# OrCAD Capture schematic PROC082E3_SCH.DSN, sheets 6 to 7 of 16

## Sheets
6 06. FPD_LINK_SER3: size C; title: FPD_LINK_SER3
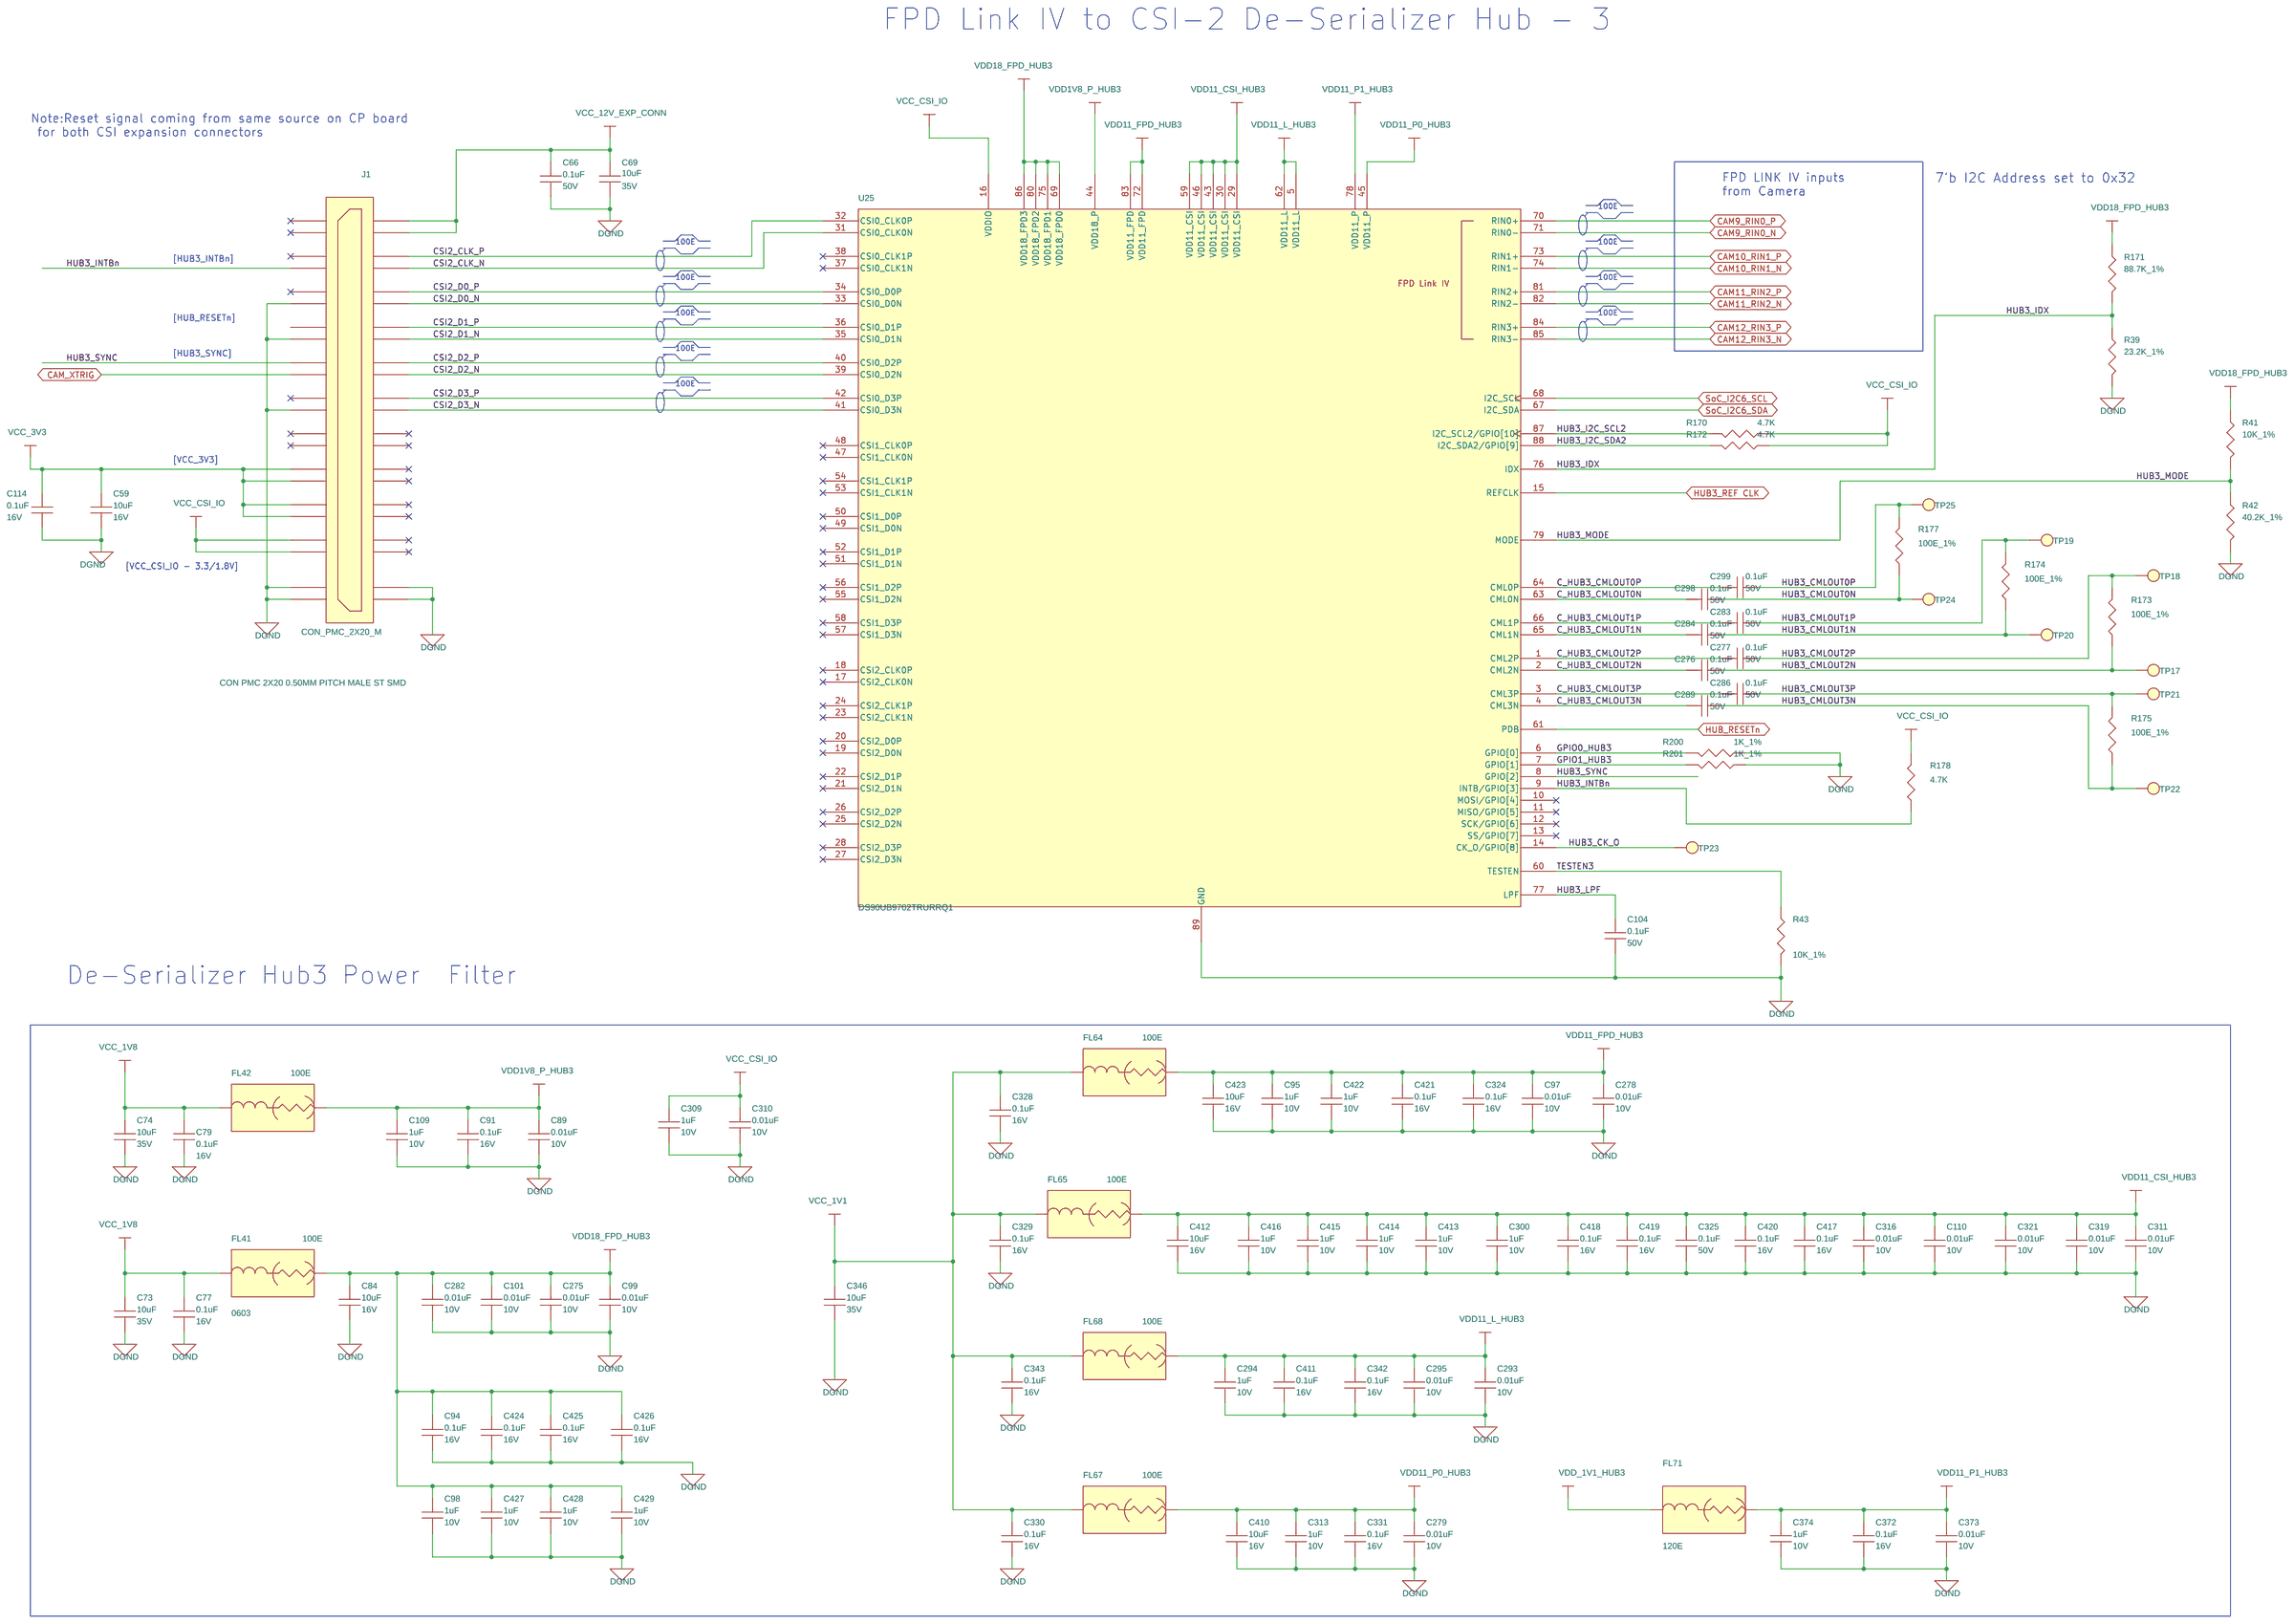
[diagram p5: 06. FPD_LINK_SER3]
7 07. FPD_LINK_971: size C; title: FUSION2_CONN & FPD_LINK_SER1
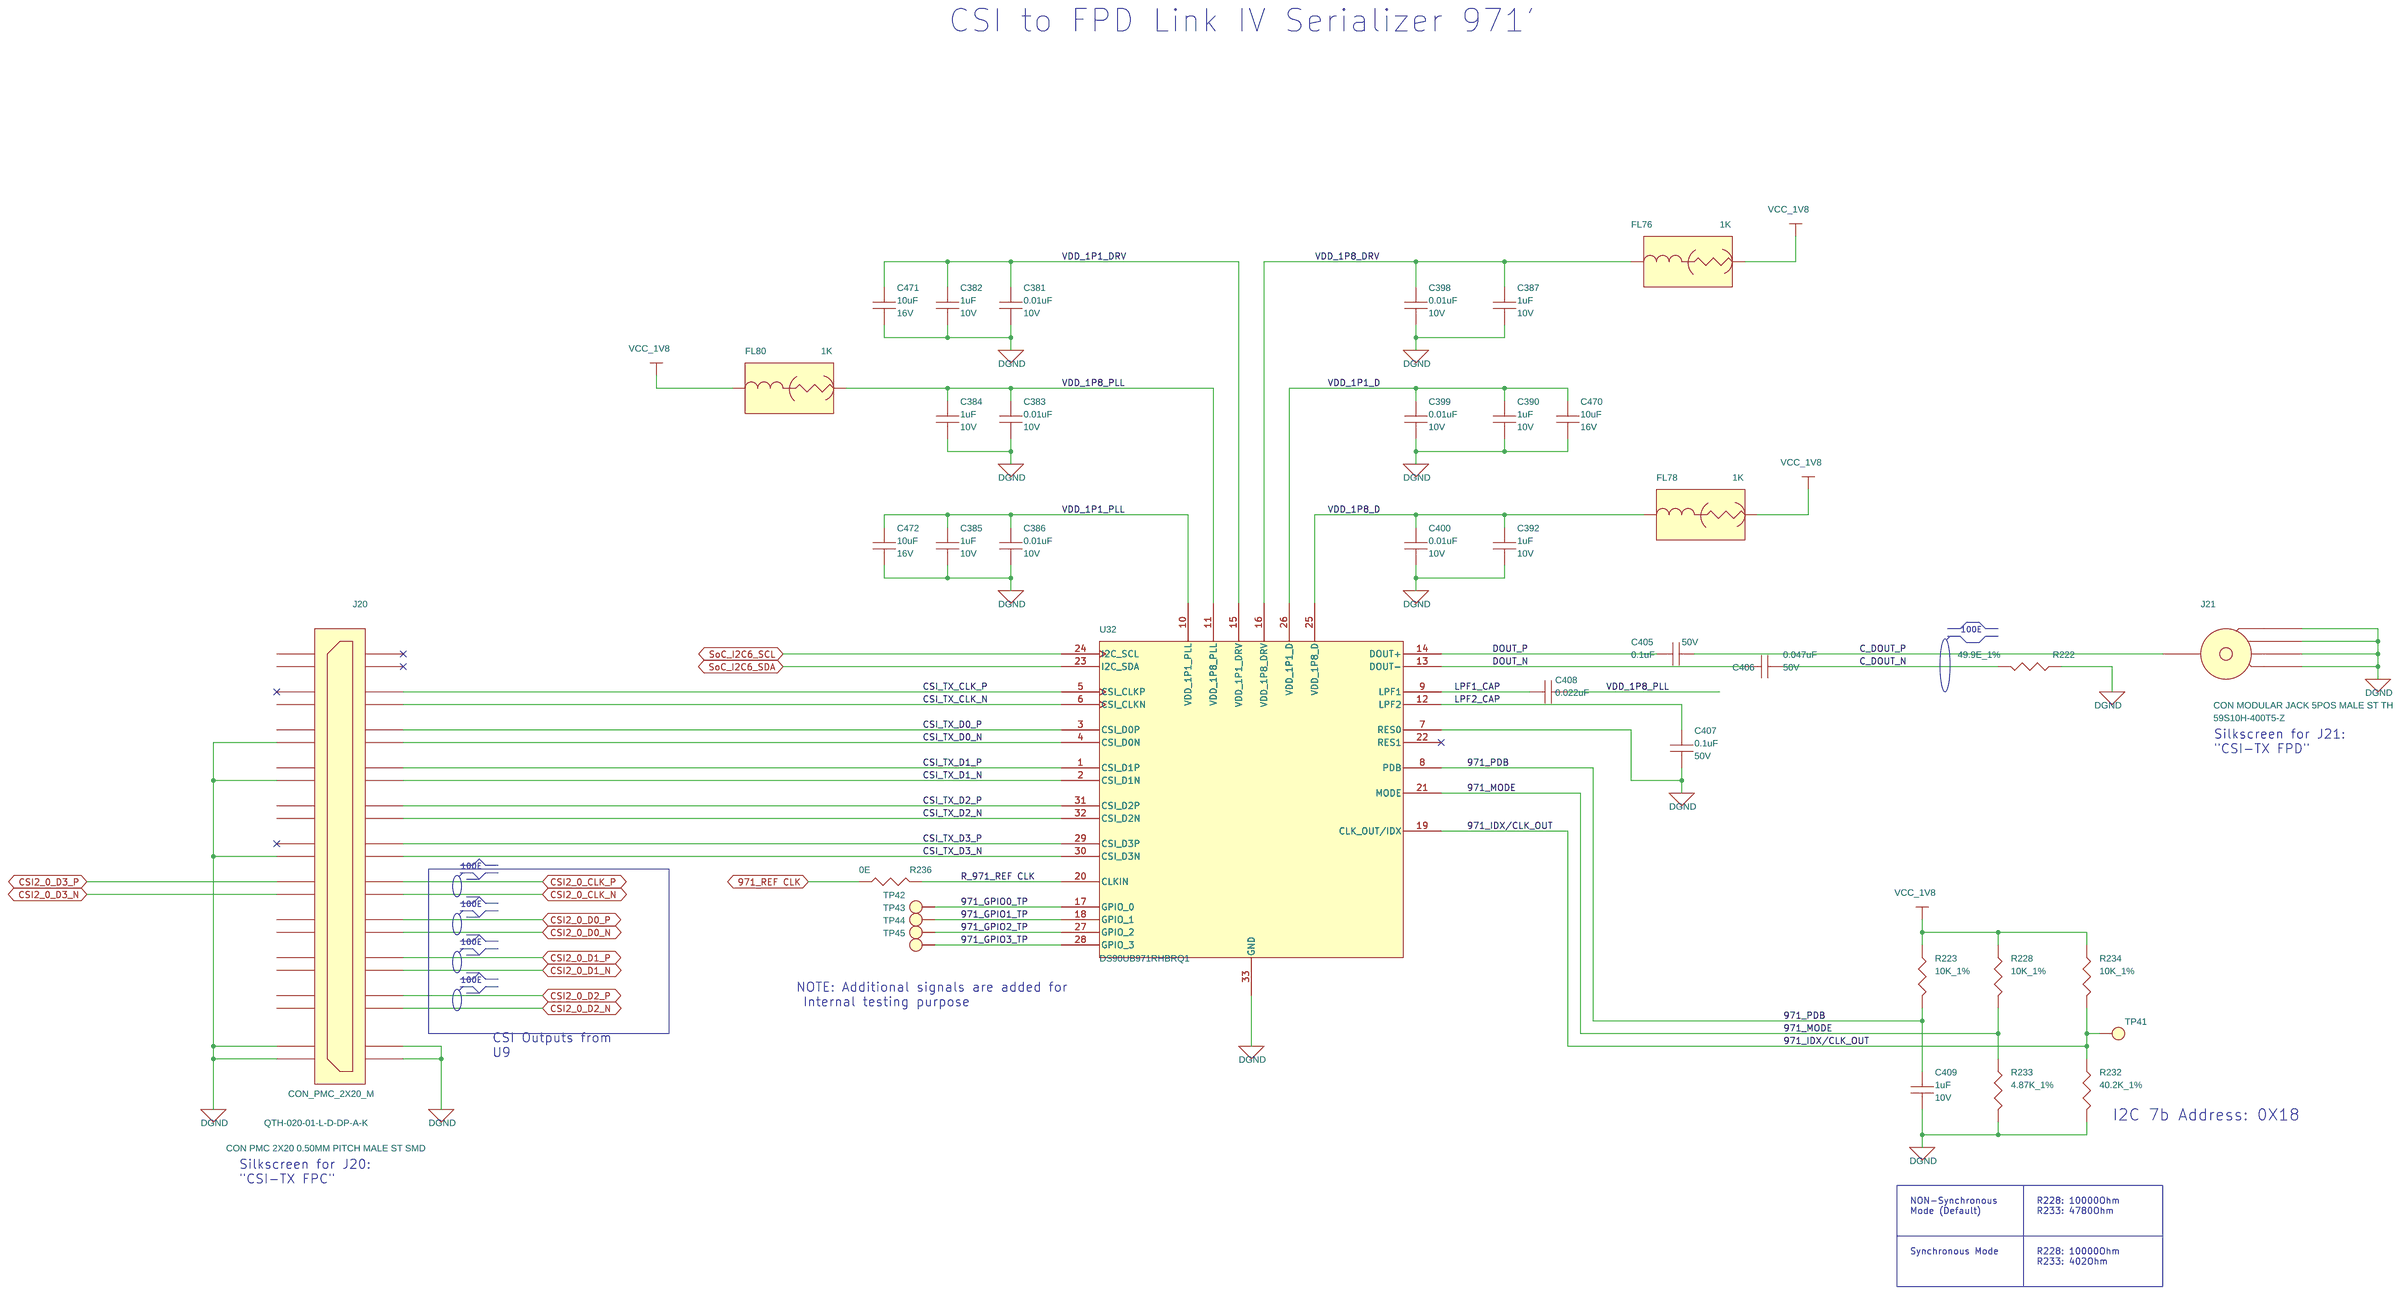
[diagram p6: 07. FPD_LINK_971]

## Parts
sheet 06. FPD_LINK_SER3
C59  10uF  [CAP0603_1]
C66  0.1uF  [CAP0402_0-75]
C69  10uF  [CAP1206_1]
C73  10uF  [CAP1206_1]
C74  10uF  [CAP1206_1]
C77  0.1uF  [CAP0402_0-75]
C79  0.1uF  [CAP0402_0-75]
C84  10uF  [CAP0603_1]
C89  0.01uF  [CAP0201_0-5]
C91  0.1uF  [CAP0402_0-75]
C94  0.1uF  [CAP0402_0-75]
C95  1uF  [CAP0402_0-75]
C97  0.01uF  [CAP0201_0-5]
C98  1uF  [CAP0402_0-75]
C99  0.01uF  [CAP0201_0-5]
C101  0.01uF  [CAP0201_0-5]
C104  0.1uF  [CAP0402_0-75]
C109  1uF  [CAP0402_0-75]
C110  0.01uF  [CAP0201_0-5]
C114  0.1uF  [CAP0402_0-75]
C275  0.01uF  [CAP0201_0-5]
C276  0.1uF  [CAP0402_0-75]
C277  0.1uF  [CAP0402_0-75]
C278  0.01uF  [CAP0201_0-5]
C279  0.01uF  [CAP0201_0-5]
C282  0.01uF  [CAP0201_0-5]
C283  0.1uF  [CAP0402_0-75]
C284  0.1uF  [CAP0402_0-75]
C286  0.1uF  [CAP0402_0-75]
C289  0.1uF  [CAP0402_0-75]
C293  0.01uF  [CAP0201_0-5]
C294  1uF  [CAP0402_0-75]
C295  0.01uF  [CAP0201_0-5]
C298  0.1uF  [CAP0402_0-75]
C299  0.1uF  [CAP0402_0-75]
C300  1uF  [CAP0402_0-75]
C309  1uF  [CAP0402_0-75]
C310  0.01uF  [CAP0201_0-5]
C311  0.01uF  [CAP0201_0-5]
C313  1uF  [CAP0402_0-75]
C316  0.01uF  [CAP0201_0-5]
C319  0.01uF  [CAP0201_0-5]
C321  0.01uF  [CAP0201_0-5]
C324  0.1uF  [CAP0402_0-75]
C325  0.1uF  [CAP0402_0-75]
C328  0.1uF  [CAP0402_0-75]
C329  0.1uF  [CAP0402_0-75]
C330  0.1uF  [CAP0402_0-75]
C331  0.1uF  [CAP0402_0-75]
C342  0.1uF  [CAP0402_0-75]
C343  0.1uF  [CAP0402_0-75]
C346  10uF  [CAP1206_1]
C372  0.1uF  [CAP0402_0-75]
C373  0.01uF  [CAP0201_0-5]
C374  1uF  [CAP0402_0-75]
C410  10uF  [CAP0603_1]
C411  0.1uF  [CAP0402_0-75]
C412  10uF  [CAP0603_1]
C413  1uF  [CAP0402_0-75]
C414  1uF  [CAP0402_0-75]
C415  1uF  [CAP0402_0-75]
C416  1uF  [CAP0402_0-75]
C417  0.1uF  [CAP0402_0-75]
C418  0.1uF  [CAP0402_0-75]
C419  0.1uF  [CAP0402_0-75]
C420  0.1uF  [CAP0402_0-75]
C421  0.1uF  [CAP0402_0-75]
C422  1uF  [CAP0402_0-75]
C423  10uF  [CAP0603_1]
C424  0.1uF  [CAP0402_0-75]
C425  0.1uF  [CAP0402_0-75]
C426  0.1uF  [CAP0402_0-75]
C427  1uF  [CAP0402_0-75]
C428  1uF  [CAP0402_0-75]
C429  1uF  [CAP0402_0-75]
FL41  100E  [EMIFIL_BLM18R_0603]
FL42  100E  [EMIFIL_BLM18R_0603]
FL64  100E  [EMIFIL_BLM18R_0603]
FL65  100E  [EMIFIL_BLM18R_0603]
FL67  100E  [EMIFIL_BLM18R_0603]
FL68  100E  [EMIFIL_BLM18R_0603]
FL71  120E  [EMIFIL_BLM15A_0402_0-6]
J1  CON_PMC_2X20_M  [CON_PMC2X20_QTH-020-01-D-DP-A_P_S_S_4-4]
R39  23.2K_1%  [RES0402_0-5]
R41  10K_1%  [RES0402_0-5]
R42  40.2K_1%  [RES0402_0-5]
R43  10K_1%  [RES0402_0-5]
R170  4.7K  [RES0402_0-5]
R171  88.7K_1%  [RES0402_0-5]
R172  4.7K  [RES0402_0-5]
R173  100E_1%  [RES0402_0-5]
R174  100E_1%  [RES0402_0-5]
R175  100E_1%  [RES0402_0-5]
R177  100E_1%  [RES0402_0-5]
R178  4.7K  [RES0402_0-5]
R200  1K_1%  [RES0402_0-5]
R201  1K_1%  [RES0402_0-5]
TP17  TP40_SMD  [TP40_SMD]
TP18  TP40_SMD  [TP40_SMD]
TP19  TP40_SMD  [TP40_SMD]
TP20  TP40_SMD  [TP40_SMD]
TP21  TP40_SMD  [TP40_SMD]
TP22  TP40_SMD  [TP40_SMD]
TP23  TP40_SMD  [TP40_SMD]
TP24  TP40_SMD  [TP40_SMD]
TP25  TP40_SMD  [TP40_SMD]
U25  DS90UB9702TRURRQ1  [QFN88_19-68_480X480_0-9_EP6-8]
sheet 07. FPD_LINK_971
C381  0.01uF  [CAP0201_0-5]
C382  1uF  [CAP0402_0-75]
C383  0.01uF  [CAP0201_0-5]
C384  1uF  [CAP0402_0-75]
C385  1uF  [CAP0402_0-75]
C386  0.01uF  [CAP0201_0-5]
C387  1uF  [CAP0402_0-75]
C390  1uF  [CAP0402_0-75]
C392  1uF  [CAP0402_0-75]
C398  0.01uF  [CAP0201_0-5]
C399  0.01uF  [CAP0201_0-5]
C400  0.01uF  [CAP0201_0-5]
C405  0.1uF  [CAP0402_0-75]
C406  0.047uF  [CAP0402_0-75]
C407  0.1uF  [CAP0402_0-75]
C408  0.022uF  [CAP0402_0-75]
C409  1uF  [CAP0402_0-75]
C470  10uF  [CAP0603_1]
C471  10uF  [CAP0603_1]
C472  10uF  [CAP0603_1]
FL76  1K  [EMIFIL_BLM15A_0402_0-6]
FL78  1K  [EMIFIL_BLM15A_0402_0-6]
FL80  1K  [EMIFIL_BLM15A_0402_0-6]
J20  CON_PMC_2X20_M  [CON_PMC2X20_QTH-020-01-D-DP-A_P_S_S_4-4]
J21  CON_JACK5_59S10H-400T5  [CON_JACK5_59S10H-400T5-Z_P_S_T_12-5]
R222  49.9E_1%  [RES0402_0-5]
R223  10K_1%  [RES0402_0-5]
R228  10K_1%  [RES0402_0-5]
R232  40.2K_1%  [RES0402_0-5]
R233  4.87K_1%  [RES0402_0-5]
R234  10K_1%  [RES0402_0-5]
R236  0E  [RES0402_0-5]
TP41  TP40_SMD  [TP40_SMD]
TP42  TP40_SMD  [TP40_SMD]
TP43  TP40_SMD  [TP40_SMD]
TP44  TP40_SMD  [TP40_SMD]
TP45  TP40_SMD  [TP40_SMD]
U32  DS90UB971RHBRQ1  [QFN32_19-68_200X200_1_EP3-8]

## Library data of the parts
C59 C84 C410 C412 C423 C470-C472 = CAP: CAP CERAMIC 10uF 16V 20% X6S 0603; Chkd/date: VASANTHA/170117; Crtd /date: VASANTHA/170117; Custom_Duty: 15%; Customs_HS_Code: 85322990; Distributor_name: DIGIKEY; Distributor_part_number: 490-7198-1-ND; Footprint Path: Y:\MIS_DATABASE\Library\ALTIUM_TOOL\PCB_FOOTPRINTS\Altium_Footprint_Lib.PcbLib; Height: 0.90MM; Library Path: Y:\MIS_DATABASE\Library\ALTIUM_TOOL\SCHEMATICS_PARTS\MS_DISCRETE_Library.schlib; Mfr_name: MURATA; Mfr_part_number: GRM188C81C106MA73D; Mistral Part No: 120017010004-R; Package: 0603; Part_type: CAPACITORS\CERAMIC; Project: TRMM_SMART-M_PS; RoHS: RoHS; Temperature: -55°C+105°C; Tolerance: 20%; Voltage: 16V; Wattage: NA; Weight: 6.3mg; Datasheet: Y:\MIS_DATABASE\DATASHEETS\CAPACITORS\MURATA-GXX-SER_NOV17.PDF
C66 C104 C276 C277 C283 C284 C286 C289 C298 C299 C325 C405 C407 = CAP: CAP CERAMIC 0.1uF 50V 10% X7R 0402; Chkd/date: MANIRAJA/131217; Crtd /date: ALVY/131217; Custom_Duty: 15%; Customs_HS_Code: 85322990; Distributor_name: DIGIKEY; Distributor_part_number: 478-10043-1-ND; Footprint Path: Y:\MIS_DATABASE\Library\ALTIUM_TOOL\PCB_FOOTPRINTS\Altium_Footprint_Lib.PcbLib; Height: 0.56MM; Library Path: Y:\MIS_DATABASE\Library\ALTIUM_TOOL\SCHEMATICS_PARTS\MS_DISCRETE_Library.schlib; Mfr_name: AVX CORPORATION; Mfr_part_number: 04025C104KAT2A; Mistral Part No: 120011100014-R; Package: 0402; Part_type: CAPACITORS\CERAMIC; Project: ASL_LIU_TYPE-II; RoHS: RoHS; Temperature: -55°C+125°C; Tolerance: 10%; Voltage: 50V; Wattage: NA; Weight: 0.65mg; Datasheet: Y:\MIS_DATABASE\DATASHEETS\CAPACITORS\AVX_MLC.PDF
C69 C73 C74 C346 = CAP: CAP CERAMIC 10uF 35V 10% X5R 1206; Chkd/date: MANIRAJA/130618; Crtd /date: MANIRAJA/130618; Custom_Duty: 15%; Customs_HS_Code: 85322990; Distributor_name: DIGIKEY; Distributor_part_number: 490-9964-1-ND; Footprint Path: Y:\MIS_DATABASE\Library\ALTIUM_TOOL\PCB_FOOTPRINTS\Altium_Footprint_Lib.PcbLib; Height: 0.95MM; Library Path: Y:\MIS_DATABASE\Library\ALTIUM_TOOL\SCHEMATICS_PARTS\MS_DISCRETE_Library.schlib; Mfr_name: MURATA; Mfr_part_number: GRM319R6YA106KA12D; Mistral Part No: 120018060022-R; Package: 1206; Part_type: CAPACITORS\CERAMIC; Project: MYTHIC_PCIE_DB; RoHS: RoHS; Temperature: -55°C+85°C; Tolerance: 10%; Voltage: 35V; Wattage: NA; Weight: 40mg; Datasheet: Y:\MIS_DATABASE\DATASHEETS\CAPACITORS\GRM319R6YA106KA12D.PDF
C77 C79 C91 C94 C114 C324 C328-C331 C342 C343 C372 C411 C417-C421 C424-C426 = CAP: CAP CERAMIC 0.1uF 16V 5% X7R AUTO 0402; Automotive Alternate_mfr_name: TDK; Automotive Alternate_mfr_part_number: CGA2B1X7R1C104K050BC; Chkd/date: MANIRAJA/241018; Crtd /date: ALVY/241018; Custom_Duty: 15%; Customs_HS_Code: 85322990; Direct Alternate_mfr_name: TDK; Direct Alternate_mfr_part_number: CGA2B1X7R1C104K050BC; Distributor_name: DIGIKEY; Distributor_part_number: 490-16433-1-ND; Footprint Path: Y:\MIS_DATABASE\Library\ALTIUM_TOOL\PCB_FOOTPRINTS\Altium_Footprint_Lib.PcbLib; Height: 0.55MM; Library Path: Y:\MIS_DATABASE\Library\ALTIUM_TOOL\SCHEMATICS_PARTS\MS_DISCRETE_Library.schlib; Mfr_name: MURATA; Mfr_part_number: GCM155R71C104JA55D; Mistral Part No: 120018100055-R; Package: 0402; Part_type: CAPACITORS\CERAMIC; Project: TI_J7ES_EVM_CP; RoHS: RoHS; Temperature: -55°C+125°C; Tolerance: 5%; Voltage: 16V; Wattage: NA; Weight: 6mg; Datasheet: Y:\MIS_DATABASE\DATASHEETS\CAPACITORS\GCM155R71C104JA55D.PDF
C89 C97 C99 C101 C110 C275 C278 C279 C282 C293 C295 C310 C311 C316 C319 C321 C373 C381 C383 C386 C398-C400 = CAP: CAP CERAMIC 0.01uF 10V 10% X5R 0201; Chkd/date: VASANTHA/270117; Crtd /date: MAZHAR/090909; Custom_Duty: 15%; Customs_HS_Code: 85322990; Distributor_name: DIGIKEY; Distributor_part_number: 490-3166-1-ND; Footprint Path: Y:\MIS_DATABASE\Library\ALTIUM_TOOL\PCB_FOOTPRINTS\Altium_Footprint_Lib.PcbLib; Footprint Ref: CAP0402_0-75; Height: 0.33MM; Library Path: Y:\MIS_DATABASE\Library\ALTIUM_TOOL\SCHEMATICS_PARTS\MS_DISCRETE_Library.schlib; Mfr_name: MURATA; Mfr_part_number: GRM033R61A103KA01D; Mistral Part No: 120011010015-R; Package: 0201; Part_type: CAPACITORS\CERAMIC; Project: VMEFMCD; RoHS: RoHS; Temperature: -55°C+85°C; Tolerance: 10%; Voltage: 10V; Wattage: NA; Weight: 0.33mg; Datasheet: Y:\MIS_DATABASE\DATASHEETS\CAPACITORS\MURATA-GXX-SER_NOV17.PDF
C95 C98 C109 C294 C300 C309 C313 C374 C382 C384 C385 C387 C390 C392 C409 C413-C416 C422 C427-C429 = CAP: CAP CERAMIC 1uF 10V 10% X7S AUTO 0402; Chkd/date: MANIRAJA/100918; Crtd /date: ALVY/100918; Custom_Duty: 15%; Customs_HS_Code: 85322990; Distributor_name: DIGIKEY; Distributor_part_number: 490-13409-1-ND; Footprint Path: Y:\MIS_DATABASE\Library\ALTIUM_TOOL\PCB_FOOTPRINTS\Altium_Footprint_Lib.PcbLib; Footprint Ref: CAP0402_0-5; Height: 0.70MM; Library Path: Y:\MIS_DATABASE\Library\ALTIUM_TOOL\SCHEMATICS_PARTS\MS_DISCRETE_Library.schlib; Mfr_name: MURATA; Mfr_part_number: GCM155C71A105KE38D; Mistral Part No: 120018090021-R; Package: 0402; Part_type: CAPACITORS\CERAMIC; Project: SMART-M_SCRIPTALK_PB; RoHS: RoHS; Temperature: -55°C+125°C; Tolerance: 10%; Voltage: 10V; Wattage: NA; Weight: 6mg; Datasheet: Y:\MIS_DATABASE\DATASHEETS\CAPACITORS\MURATA-GCM-SER.PDF
FL41 FL42 FL64 FL65 FL67 FL68 = EMIFILTER_IND: PASSIVE FILTER EMI 100E 2A 0603; Chkd/date: BAVISH/170811; Crtd /date: CHAITHANYA/170811; Custom_Duty: 24%; Customs_HS_Code: 85437099; Distributor_name: DIGIKEY; Distributor_part_number: BLM18EG101TN1D-ND; Footprint Path: Y:\MIS_DATABASE\Library\ALTIUM_TOOL\PCB_FOOTPRINTS\Altium_Footprint_Lib.PcbLib; Height: 0.65MM; Library Path: Y:\MIS_DATABASE\Library\ALTIUM_TOOL\SCHEMATICS_PARTS\MS_FILTER_Library.schlib; Mfr_name: MURATA; Mfr_part_number: BLM18EG101TN1D; Mistral Part No: 130011080028-R; Package: 0603; Part_type: FILTER; Project: CPCI3GADC_CARD; RoHS: RoHS; Temperature: -55°C+125°C; Tolerance: NA; Voltage: NA; Wattage: NA; Weight: NA; Datasheet: Y:\MIS_DATABASE\DATASHEETS\DISCRETES\INDUCTORS\BLM18E.PDF
FL71 = EMIFILTER_IND: IND FERRITE BEAD CHIP 120E 1.3A 0402; Chkd/date: VASANTHA/010117; Crtd /date: CHAITHANYA/150312; Custom_Duty: 24%; Customs_HS_Code: 85437099; Distributor_name: DIGIKEY; Distributor_part_number: 490-5203-1-ND; Footprint Path: Y:\MIS_DATABASE\Library\ALTIUM_TOOL\PCB_FOOTPRINTS\Altium_Footprint_Lib.PcbLib; Height: 0.55MM; Library Path: Y:\MIS_DATABASE\Library\ALTIUM_TOOL\SCHEMATICS_PARTS\MS_FILTER_Library.schlib; Mfr_name: MURATA; Mfr_part_number: BLM15PD121SN1D; Mistral Part No: 130012030043-R; Package: 0402; Part_type: FILTER; Project: GEN_3-8; RoHS: RoHS; Temperature: -55°C+125°C; Tolerance: 25%; Voltage: NA; Wattage: NA; Weight: 0.65mg; Datasheet: Y:\MIS_DATABASE\DATASHEETS\DISCRETES\INDUCTORS\BLM15X-SER.PDF
J1 J20 = CON_20X2_QTH-020-DP: CON PMC 2X20 0.50MM PITCH MALE ST SMD; Chkd/date: MANIRAJA/251018; Crtd /date: ALVY/251018; Custom_Duty: 24%; Customs_HS_Code: 85369090; Distributor_name: DIGIKEY; Distributor_part_number: SAM10667-ND; Footprint Path: Y:\MIS_DATABASE\Library\ALTIUM_TOOL\PCB_FOOTPRINTS\Altium_Footprint_Lib.PcbLib; Height: 4.35MM; Library Path: Y:\MIS_DATABASE\Library\ALTIUM_TOOL\SCHEMATICS_PARTS\MS_CONNECTOR_Library.schlib; Mfr_name: SAMTEC; Mfr_part_number: QTH-020-01-L-D-DP-A-K; Mistral Part No: 150018100046-R; Package: SMD; Part_type: CONNECTOR\PMC; Project: TI_J7ES_EVM_CP; RoHS: RoHS; Temperature: -55°C+125°C; Tolerance: NA; Voltage: NA; Wattage: NA; Weight: NA; Datasheet: Y:\MIS_DATABASE\DATASHEETS\CONNECTORS\SAM-QTH-DP.PDF
R39 = RESISTOR: RES 23.2K 1/10W 1% 0402; Chkd/date: VINITHA/291211; Crtd /date: BAVISH/080611; Custom_Duty: 15%; Customs_HS_Code: 85332119; Distributor_name: DIGIKEY; Distributor_part_number: P23.2KLCT-ND; Footprint Path: Y:\MIS_DATABASE\Library\ALTIUM_TOOL\PCB_FOOTPRINTS\Altium_Footprint_Lib.PcbLib; Height: 0.40MM; Library Path: Y:\MIS_DATABASE\Library\ALTIUM_TOOL\SCHEMATICS_PARTS\MS_DISCRETE_Library.schlib; Mfr_name: PANASONIC-ECG; Mfr_part_number: ERJ-2RKF2322X; Mistral Part No: 110011060026-R; Package: 0402; Part_type: RESISTORS\FIXED; Project: ACRO_DM3730; RoHS: RoHS; Temperature: -55°C+155°C; Tolerance: 1%; Voltage: NA; Wattage: 1/10W; Weight: 0.8mg; Datasheet: Y:\MIS_DATABASE\DATASHEETS\RESISTORS\PAN-ERJSER_NOV17.PDF
R41 R43 R223 R228 R234 = RESISTOR: RES 10K 1/16W 1% 0402; Chkd/date: VASANTHA/201216; Crtd /date: GEETHA/290506; Custom_Duty: 15%; Customs_HS_Code: 85332119; Distributor_name: DIGIKEY; Distributor_part_number: 311-10.0KLRTR-ND; Footprint Path: Y:\MIS_DATABASE\Library\ALTIUM_TOOL\PCB_FOOTPRINTS\Altium_Footprint_Lib.PcbLib; Height: 0.40MM; Library Path: Y:\MIS_DATABASE\Library\ALTIUM_TOOL\SCHEMATICS_PARTS\MS_DISCRETE_Library.schlib; Mfr_name: YAGEO AMERICA; Mfr_part_number: RC0402FR-0710KL; Mistral Part No: 110015090015-R; Package: 0402; Part_type: RESISTORS\FIXED; Project: VOCERA; RoHS: RoHS; Temperature: -55°C+155°C; Tolerance: 1%; Voltage: NA; Wattage: 1/16W; Weight: 0.65mg; Datasheet: Y:\MIS_DATABASE\DATASHEETS\RESISTORS\RCXXXXL-SER_MAR18.PDF
R42 R232 = RESISTOR: RES 40.2K 1/16W 1% 0402; Chkd/date: VASANTHA/291216; Crtd /date: MAZHAR/170505; Custom_Duty: 15%; Customs_HS_Code: 85332119; Distributor_name: DIGIKEY; Distributor_part_number: 311-40.2KLRDKR-ND; Footprint Path: Y:\MIS_DATABASE\Library\ALTIUM_TOOL\PCB_FOOTPRINTS\Altium_Footprint_Lib.PcbLib; Height: 0.40MM; Library Path: Y:\MIS_DATABASE\Library\ALTIUM_TOOL\SCHEMATICS_PARTS\MS_DISCRETE_Library.schlib; Mfr_name: YAGEO AMERICA; Mfr_part_number: RC0402FR-0740K2L; Mistral Part No: 110009030811-R; Package: 0402; Part_type: RESISTORS\FIXED; Project: G4SLIM; RoHS: RoHS; Temperature: -55°C+155°C; Tolerance: 1%; Voltage: NA; Wattage: 1/16W; Weight: 0.65mg; Datasheet: Y:\MIS_DATABASE\DATASHEETS\RESISTORS\RCXXXXL-SER_MAR18.PDF
R170 R172 R178 = RESISTOR: RES 4.7K 1/16W 5% 0402; Chkd/date: VASANTHA/281216; Crtd /date: BAVISH/010611; Custom_Duty: 15%; Customs_HS_Code: 85332119; Distributor_name: DIGIKEY; Distributor_part_number: 541-4.7KJCT-ND; Footprint Path: Y:\MIS_DATABASE\Library\ALTIUM_TOOL\PCB_FOOTPRINTS\Altium_Footprint_Lib.PcbLib; Height: 0.40MM; Library Path: Y:\MIS_DATABASE\Library\ALTIUM_TOOL\SCHEMATICS_PARTS\MS_DISCRETE_Library.schlib; Mfr_name: VISHAY; Mfr_part_number: CRCW04024K70JNED; Mistral Part No: 110011060001-R; Package: 0402; Part_type: RESISTORS\FIXED; Project: AM4515_EVM_LCD; RoHS: RoHS; Temperature: -55°C+155°C; Tolerance: 5%; Voltage: NA; Wattage: 1/16W; Weight: 0.65mg; Datasheet: Y:\MIS_DATABASE\DATASHEETS\RESISTORS\CRCW0603.PDF
R171 = RESISTOR: RES 88.7K 1/10W 1% 0402; Chkd/date: MANIRAJA/220817; Crtd /date: MANIRAJA/220817; Custom_Duty: 15%; Customs_HS_Code: 85332119; Distributor_name: DIGIKEY; Distributor_part_number: P88.7KLCT-ND; Footprint Path: Y:\MIS_DATABASE\Library\ALTIUM_TOOL\PCB_FOOTPRINTS\Altium_Footprint_Lib.PcbLib; Height: 0.40MM; Library Path: Y:\MIS_DATABASE\Library\ALTIUM_TOOL\SCHEMATICS_PARTS\MS_DISCRETE_Library.schlib; Mfr_name: PANASONIC-ECG; Mfr_part_number: ERJ-2RKF8872X; Mistral Part No: 110017080021-R; Package: 0402; Part_type: RESISTORS\FIXED; Project: RSAPR_TYPE-II_3U-HSADC; RoHS: RoHS; Temperature: -55°C+155°C; Tolerance: 1%; Voltage: NA; Wattage: 1/10W; Weight: 0.8mg; Datasheet: Y:\MIS_DATABASE\DATASHEETS\RESISTORS\PAN-ERJSER_NOV17.PDF
R173-R175 R177 = RESISTOR: RES 100E 1/10W 1% 0402; Chkd/date: MANIRAJA/130617; Crtd /date: JEBRAN/040715; Custom_Duty: 15%; Customs_HS_Code: 85332119; Distributor_name: DIGIKEY; Distributor_part_number: P100LCT-ND; Footprint Path: Y:\MIS_DATABASE\Library\ALTIUM_TOOL\PCB_FOOTPRINTS\Altium_Footprint_Lib.PcbLib; Height: 0.40MM; Library Path: Y:\MIS_DATABASE\Library\ALTIUM_TOOL\SCHEMATICS_PARTS\MS_DISCRETE_Library.schlib; Mfr_name: PANASONIC-ECG; Mfr_part_number: ERJ-2RKF1000X; Mistral Part No: 110018020036-R; Package: 0402; Part_type: RESISTORS\FIXED; Project: CYPHY_FVB; RoHS: RoHS; Temperature: -55°C+155°C; Tolerance: 1%; Voltage: NA; Wattage: 1/10W; Weight: 0.8mg; Datasheet: Y:\MIS_DATABASE\DATASHEETS\RESISTORS\PAN-ERJSER_NOV17.PDF
R200 R201 = RESISTOR: RES 1K 1/10W 1% 0402; Chkd/date: VASANTHA/281216; Crtd /date: MAZHAR/150506; Custom_Duty: 15%; Customs_HS_Code: 85332119; Distributor_name: DIGIKEY; Distributor_part_number: P1.00KLCT-ND; Footprint Path: Y:\MIS_DATABASE\Library\ALTIUM_TOOL\PCB_FOOTPRINTS\Altium_Footprint_Lib.PcbLib; Height: 0.40MM; Library Path: Y:\MIS_DATABASE\Library\ALTIUM_TOOL\SCHEMATICS_PARTS\MS_DISCRETE_Library.schlib; Mfr_name: PANASONIC-ECG; Mfr_part_number: ERJ-2RKF1001X; Mistral Part No: 110009030411-R; Package: 0402; Part_type: RESISTORS\FIXED; Project: VOCERA; RoHS: RoHS; Temperature: -55°C+155°C; Tolerance: 1%; Voltage: NA; Wattage: 1/10W; Weight: 0.8mg; Datasheet: Y:\MIS_DATABASE\DATASHEETS\RESISTORS\PAN-ERJSER_NOV17.PDF
TP17-TP25 TP41-TP45 = TESTPOINT: TESTPOINT CIR 40 SMD; Chkd/date: MAZHAR/190505; Crtd /date: MAZHAR/190505; Distributor_name: NA; Distributor_part_number: NA; Footprint Path: Y:\MIS_DATABASE\Library\ALTIUM_TOOL\PCB_FOOTPRINTS\Altium_Footprint_Lib.PcbLib; Height: NA; Library Path: Y:\MIS_DATABASE\Library\ALTIUM_TOOL\SCHEMATICS_PARTS\MS_DISCRETE_Library.schlib; MECHANICAL 3D STEP FILE: NA; Mfr_name: LOCAL; Mistral Part No: 130009030933; Package: SMD; Project: RAINIER-3; RoHS: NA; Temperature: NA; Tolerance: NA; Voltage: NA; Wattage: NA; Weight: NA; Datasheet: NA
U25 = DS90UB9702-Q1_VQFNP88: IC 8.4Gbps 4 FPD-LINK IV DESERIALIZER HUB WITH DUAL CSI-2 O/P PORTS FOR 8MP+ CAMERAS VQFNP88; Chkd/date: MANIRAJA/230718; Crtd /date: ALVY/200718; Custom_Duty: 15%; Customs_HS_Code: 85423100; Distributor_name: NA; Distributor_part_number: NA; Footprint Path: Y:\MIS_DATABASE\Library\ALTIUM_TOOL\PCB_FOOTPRINTS\Altium_Footprint_Lib.PcbLib; Height: 0.90MM; Library Path: Y:\MIS_DATABASE\Library\ALTIUM_TOOL\SCHEMATICS_PARTS\MS_MISCINTERFACE_Library.schlib; Mfr_name: TEXAS INSTRUMENTS; Mistral Part No: 141018070009; Package: VQFNP88; Part_type: ICS\INTERFACE; Project: TI_J7ES_EVM_FUSION2_SER_CAP; RoHS: NA; Temperature: -40°C+105°C; Tolerance: NA; Voltage: NA; Wattage: NA; Weight: NA; Datasheet: Y:\MIS_DATABASE\DATASHEETS\ICS\INTERFACE\DS90UB9702-Q1_MAR19.PDF
C406 = CAP: CAP CERAMIC 0.047uF 50V 10% X7R 0402; Chkd/date: MANIRAJA/240118; Crtd /date: MANIRAJA/240118; Custom_Duty: 15%; Customs_HS_Code: 85322990; Distributor_name: DIGIKEY; Distributor_part_number: GRM155R71H473KE14J-ND; Footprint Path: Y:\MIS_DATABASE\Library\ALTIUM_TOOL\PCB_FOOTPRINTS\Altium_Footprint_Lib.PcbLib; Height: 0.55MM; Library Path: Y:\MIS_DATABASE\Library\ALTIUM_TOOL\SCHEMATICS_PARTS\MS_DISCRETE_Library.schlib; Mfr_name: MURATA; Mfr_part_number: GRM155R71H473KE14J; Mistral Part No: 120018010011-R; Package: 0402; Part_type: CAPACITORS\CERAMIC; Project: TI_MAXIE_CPB; RoHS: RoHS; Temperature: -55°C+125°C; Tolerance: 10%; Voltage: 50V; Wattage: NA; Weight: 6mg; Datasheet: Y:\MIS_DATABASE\DATASHEETS\CAPACITORS\GRM155R71H473KE14.PDF
C408 = CAP: CAP CERAMIC 0.022uF 50V 10% X7R AUTO 0402; Chkd/date: MAZHAR/301208; Crtd /date: USMAN/051108; Custom_Duty: 15%; Customs_HS_Code: 85322990; Distributor_name: DIGIKEY; Distributor_part_number: 490-4763-1-ND; Footprint Path: Y:\MIS_DATABASE\Library\ALTIUM_TOOL\PCB_FOOTPRINTS\Altium_Footprint_Lib.PcbLib; Height: 0.55MM; Library Path: Y:\MIS_DATABASE\Library\ALTIUM_TOOL\SCHEMATICS_PARTS\MS_DISCRETE_Library.schlib; Mfr_name: MURATA; Mfr_part_number: GCM155R71H223KA55D; Mistral Part No: 120011100036-R; Package: 0402; Part_type: CAPACITORS\CERAMIC; Project: P2ER6DB; RoHS: RoHS; Temperature: -55°C+125°C; Tolerance: 10%; Voltage: 50V; Wattage: NA; Weight: 6mg; Datasheet: Y:\MIS_DATABASE\DATASHEETS\CAPACITORS\GCM155R71H223KA55.PDF
FL76 FL78 FL80 = EMIFILTER_IND: IND FERRITE BEAD CHIP 1K 350mA 0402; Chkd/date: MANIRAJA/180920; Crtd /date: ALVY/180920; Custom_Duty: 24%; Customs_HS_Code: 85437099; Distributor_name: DIGIKEY; Distributor_part_number: 490-5442-1-ND; Footprint Path: Y:\MIS_DATABASE\Library\ALTIUM_TOOL\PCB_FOOTPRINTS\Altium_Footprint_Lib.PcbLib; Height: 0.55MM; Library Path: Y:\MIS_DATABASE\Library\ALTIUM_TOOL\SCHEMATICS_PARTS\MS_FILTER_Library.schlib; Mfr_name: MURATA; Mfr_part_number: BLM15AX102SN1D; Mistral Part No: 130020090036-R; Package: 0402; Part_type: INDUCTOR; Project: TI_J7ES_EVM_FUSION2_SER_CAP; RoHS: RoHS; Temperature: -55°C+125°C; Tolerance: 25%; Voltage: NA; Wattage: NA; Weight: 1mg; Datasheet: Y:\MIS_DATABASE\DATASHEETS\DISCRETES\INDUCTORS\BLM15-SN1-SER.PDF
J21 = CON5_MCXJACK_TH: CON MODULAR JACK 5POS MALE ST TH; Chkd/date: MANIRAJA/020519; Crtd /date: MANIRAJA/020519; Custom_Duty: 24%; Customs_HS_Code: 85369090; Distributor_name: MOUSER; Distributor_part_number: 476-59S10H-400T5-Z; Footprint Path: Y:\MIS_DATABASE\Library\ALTIUM_TOOL\PCB_FOOTPRINTS\Altium_Footprint_Lib.PcbLib; Height: 12.45MM; Library Path: Y:\MIS_DATABASE\Library\ALTIUM_TOOL\SCHEMATICS_PARTS\MS_CONNECTOR_Library.schlib; Mfr_name: ROSENBERGER; Mfr_part_number: 59S10H-400T5-Z; Mistral Part No: 150019050001-R; Package: THRU-HOLE; Part_type: CONNECTOR\JACK; Project: TI_J7ES_EVM_FUSION2_SER_CAP; RoHS: RoHS; Temperature: -40°C+105°C; Tolerance: NA; Voltage: NA; Wattage: NA; Weight: 1650mg; Datasheet: Y:\MIS_DATABASE\DATASHEETS\CONNECTORS\59S10H-400T5-Y.PDF
R222 = RESISTOR: RES 49.9E 1/10W 1% 0402; Chkd/date: VASANTHA/201216; Crtd /date: MAZHAR/201005; Custom_Duty: 15%; Customs_HS_Code: 85332119; Distributor_name: DIGIKEY; Distributor_part_number: P49.9LCT-ND; Footprint Path: Y:\MIS_DATABASE\Library\ALTIUM_TOOL\PCB_FOOTPRINTS\Altium_Footprint_Lib.PcbLib; Height: 0.40MM; Library Path: Y:\MIS_DATABASE\Library\ALTIUM_TOOL\SCHEMATICS_PARTS\MS_DISCRETE_Library.schlib; Mfr_name: PANASONIC-ECG; Mfr_part_number: ERJ-2RKF49R9X; Mistral Part No: 110009030897-R; Package: 0402; Part_type: RESISTORS\FIXED; Project: RED EYE; RoHS: RoHS; Temperature: -55°C+155°C; Tolerance: 1%; Voltage: NA; Wattage: 1/10W; Weight: 0.8mg; Datasheet: Y:\MIS_DATABASE\DATASHEETS\RESISTORS\PAN-ERJSER_NOV17.PDF
R233 = RESISTOR: RES 4.87K 1/10W 1% 0402; Chkd/date: MAZHAR/150709; Crtd /date: USMAN/150109; Custom_Duty: 15%; Customs_HS_Code: 85332119; Distributor_name: DIGIKEY; Distributor_part_number: P4.87KLCT-ND; Footprint Path: Y:\MIS_DATABASE\Library\ALTIUM_TOOL\PCB_FOOTPRINTS\Altium_Footprint_Lib.PcbLib; Height: 0.40MM; Library Path: Y:\MIS_DATABASE\Library\ALTIUM_TOOL\SCHEMATICS_PARTS\MS_DISCRETE_Library.schlib; Mfr_name: PANASONIC-ECG; Mfr_part_number: ERJ-2RKF4871X; Mistral Part No: 110009030803-R; Package: 0402; Part_type: RESISTORS\FIXED; Project: BSN-II; RoHS: RoHS; Temperature: -55°C+155°C; Tolerance: 1%; Voltage: NA; Wattage: 1/10W; Weight: 0.8mg; Datasheet: Y:\MIS_DATABASE\DATASHEETS\RESISTORS\PAN-ERJSER_NOV17.PDF
R236 = RESISTOR: RES 0E 1/10W JUMPER 0402; Chkd/date: VASANTHA/061216; Crtd /date: NAVEED/201014; Custom_Duty: 15%; Customs_HS_Code: 85332119; Distributor_name: DIGIKEY; Distributor_part_number: P0.0JCT-ND; Footprint Path: Y:\MIS_DATABASE\Library\ALTIUM_TOOL\PCB_FOOTPRINTS\Altium_Footprint_Lib.PcbLib; Height: 0.40MM; IBISSP_MODLES: VALUE REPEATING 2 TIME; Library Path: Y:\MIS_DATABASE\Library\ALTIUM_TOOL\SCHEMATICS_PARTS\MS_DISCRETE_Library.schlib; Mfr_name: PANASONIC-ECG; Mfr_part_number: ERJ-2GE0R00X; Mistral Part No: 110018030052-R; Package: 0402; Part_type: RESISTORS\FIXED; Project: AEGIS POM; RoHS: RoHS; Temperature: -55°C+155°C; Tolerance: NA; Voltage: NA; Wattage: 1/10W; Weight: 0.8mg; Datasheet: Y:\MIS_DATABASE\DATASHEETS\RESISTORS\PAN-ERJSER_NOV17.PDF
U32 = DS90UB971-Q1_VQFN32: IC 8.4Gbps FPD-LINK IV SERIALIZER HUB WITH CSI-2 INTERFACE PORTS FOR 8MP+ CAMERAS RADAR VQFN32; Chkd/date: MANIRAJA/140920; Crtd /date: ALVY/140920; Custom_Duty: 15%; Customs_HS_Code: 85423100; Distributor_name: NA; Distributor_part_number: NA; Footprint Path: Y:\MIS_DATABASE\Library\ALTIUM_TOOL\PCB_FOOTPRINTS\Altium_Footprint_Lib.PcbLib; Height: 1.00MM; Library Path: Y:\MIS_DATABASE\Library\ALTIUM_TOOL\SCHEMATICS_PARTS\MS_MISCINTERFACE_Library.schlib; Mfr_name: TEXAS INSTRUMENTS; Mistral Part No: 141020090009; Package: VQFN32; Part_type: ICS\INTERFACE; Project: TI_J7ES_EVM_FUSION2_SER_CAP; RoHS: NA; Temperature: -40°C+115°C; Tolerance: NA; Voltage: NA; Wattage: NA; Weight: NA; Datasheet: Y:\MIS_DATABASE\DATASHEETS\ICS\INTERFACE\DS90UB971-Q1.PDF

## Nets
DGND: C59.2 C66.2 C69.2 C73.2 C74.2 C77.2 C79.2 C84.2 C89.2 C91.2 C94.2 C95.2 C97.2 C98.2 C99.2 C101.2 C104.2 C109.2 C110.2 C114.2 C275.2 C278.2 C279.2 C282.2 C293.2 C294.2 C295.2 C300.2 C309.2 C310.2 C311.2 C313.2 C316.2 C319.2 C321.2 C324.2 C325.2 C328.2 C329.2 C330.2 C331.2 C342.2 C343.2 C346.2 C372.2 C373.2 C374.2 C381.2 C382.2 C383.2 C384.2 C385.2 C386.2 C387.2 C390.2 C392.2 C398.2 C399.2 C400.2 C407.2 C409.2 C410.2 C411.2 C412.2 C413.2 C414.2 C415.2 C416.2 C417.2 C418.2 C419.2 C420.2 C421.2 C422.2 C423.2 C424.2 C425.2 C426.2 C427.2 C428.2 C429.2 C470.2 C471.2 C472.2 J1.12 J1.16 J1.24 J1.SH1 J1.SH2 J1.SH3 J1.SH4 J20.12 J20.16 J20.24 J20.SH1 J20.SH2 J20.SH3 J20.SH4 J21.2 J21.3 J21.4 J21.5 R39.2 R42.2 R43.2 R200.1 R201.1 R222.1 R232.2 R233.2 U25.89(GND) U32.7(RES0) U32.33(GND) ; also on sheet 4 5 8 9 10 11 13 14 15 16
VCC_1V1: C328.1 C329.1 C330.1 C343.1 C346.1 FL64.1 FL65.1 FL67.1 FL68.1 ; also on sheet 4 5 11
VCC_1V8: C73.1 C74.1 C77.1 C79.1 FL41.1 FL42.1 FL76.2 FL78.2 FL80.1 R223.1 R228.1 R234.1 ; also on sheet 4 5 10 11
VCC_3V3: C59.1 C114.1 J1.30 J1.32 J1.34 J1.36 ; also on sheet 4 10 11
VCC_12V_EXP_CONN: C66.1 C69.1 J1.1 J1.3 ; also on sheet 4 11
VCC_CSI_IO: C309.1 C310.1 J1.38 J1.40 R170.2 R172.2 R178.2 U25.16(VDDIO) ; also on sheet 4 5 10 11
VDD1V8_P_HUB3: C89.1 C91.1 C109.1 FL42.2 U25.44(VDD18_P)
VDD11_CSI_HUB3: C110.1 C300.1 C311.1 C316.1 C319.1 C321.1 C325.1 C412.1 C413.1 C414.1 C415.1 C416.1 C417.1 C418.1 C419.1 C420.1 FL65.2 U25.29(VDD11_CSI) U25.30(VDD11_CSI) U25.43(VDD11_CSI) U25.46(VDD11_CSI) U25.59(VDD11_CSI)
VDD11_FPD_HUB3: C95.1 C97.1 C278.1 C324.1 C421.1 C422.1 C423.1 FL64.2 U25.72(VDD11_FPD) U25.83(VDD11_FPD)
VDD11_L_HUB3: C293.1 C294.1 C295.1 C342.1 C411.1 FL68.2 U25.5(VDD11_L) U25.62(VDD11_L)
VDD11_P0_HUB3: C279.1 C313.1 C331.1 C410.1 FL67.2 U25.45(VDD11_P)
VDD11_P1_HUB3: C372.1 C373.1 C374.1 FL71.2 U25.78(VDD11_P)
VDD18_FPD_HUB3: C84.1 C94.1 C98.1 C99.1 C101.1 C275.1 C282.1 C424.1 C425.1 C426.1 C427.1 C428.1 C429.1 FL41.2 R41.1 R171.1 U25.69(VDD18_FPD0) U25.75(VDD18_FPD1) U25.80(VDD18_FPD2) U25.86(VDD18_FPD3)
VDD_1P1_D: C390.1 C399.1 C470.1 U32.26(VDD_1P1_D)
VDD_1P1_DRV: C381.1 C382.1 C471.1 U32.15(VDD_1P1_DRV)
VDD_1P1_PLL: C385.1 C386.1 C472.1 U32.10(VDD_1P1_PLL)
VDD_1P8_D: C392.1 C400.1 FL78.1 U32.25(VDD_1P8_D)
VDD_1P8_DRV: C387.1 C398.1 FL76.1 U32.16(VDD_1P8_DRV)
VDD_1P8_PLL: C383.1 C384.1 C408.2 FL80.2 U32.11(VDD_1P8_PLL)
VDD_1V1_HUB3: FL71.1 ; also on sheet 11
971_GPIO0_TP: TP42.1(TP) U32.17(GPIO_0)
971_GPIO1_TP: TP43.1(TP) U32.18(GPIO_1)
971_GPIO2_TP: TP44.1(TP) U32.27(GPIO_2)
971_GPIO3_TP: TP45.1(TP) U32.28(GPIO_3)
971_IDX/CLK_OUT: R232.1 R234.2 TP41.1(TP) U32.19(CLK_OUT/IDX)
971_MODE: R228.2 R233.1 U32.21(MODE)
971_PDB: C409.1 R223.2 U32.8(PDB)
971_REF CLK: R236.1 ; also on sheet 10
C_DOUT_N: C406.1 R222.2
C_DOUT_P: C405.1 J21.1
C_HUB3_CMLOUT0N: C298.2 U25.63(CML0N)
C_HUB3_CMLOUT0P: C299.2 U25.64(CML0P)
C_HUB3_CMLOUT1N: C284.2 U25.65(CML1N)
C_HUB3_CMLOUT1P: C283.2 U25.66(CML1P)
C_HUB3_CMLOUT2N: C276.2 U25.2(CML2N)
C_HUB3_CMLOUT2P: C277.2 U25.1(CML2P)
C_HUB3_CMLOUT3N: C289.2 U25.4(CML3N)
C_HUB3_CMLOUT3P: C286.2 U25.3(CML3P)
CAM9_RIN0_N: U25.71(RIN0-) ; also on sheet 9
CAM9_RIN0_P: U25.70(RIN0+) ; also on sheet 9
CAM10_RIN1_N: U25.74(RIN1-) ; also on sheet 9
CAM10_RIN1_P: U25.73(RIN1+) ; also on sheet 9
CAM11_RIN2_N: U25.82(RIN2-) ; also on sheet 9
CAM11_RIN2_P: U25.81(RIN2+) ; also on sheet 9
CAM12_RIN3_N: U25.85(RIN3-) ; also on sheet 9
CAM12_RIN3_P: U25.84(RIN3+) ; also on sheet 9
CAM_XTRIG: J1.20
CSI2_0_CLK_N: J20.27 ; also on sheet 4
CSI2_0_CLK_P: J20.25 ; also on sheet 4
CSI2_0_D0_N: J20.31 ; also on sheet 4
CSI2_0_D0_P: J20.29 ; also on sheet 4
CSI2_0_D1_N: J20.35 ; also on sheet 4
CSI2_0_D1_P: J20.33 ; also on sheet 4
CSI2_0_D2_N: J20.39 ; also on sheet 4
CSI2_0_D2_P: J20.37 ; also on sheet 4
CSI2_0_D3_N: J20.28 ; also on sheet 4
CSI2_0_D3_P: J20.26 ; also on sheet 4
CSI2_CLK_N: J1.7 U25.31(CSI0_CLK0N)
CSI2_CLK_P: J1.5 U25.32(CSI0_CLK0P)
CSI2_D0_N: J1.11 U25.33(CSI0_D0N)
CSI2_D0_P: J1.9 U25.34(CSI0_D0P)
CSI2_D1_N: J1.15 U25.35(CSI0_D1N)
CSI2_D1_P: J1.13 U25.36(CSI0_D1P)
CSI2_D2_N: J1.19 U25.39(CSI0_D2N)
CSI2_D2_P: J1.17 U25.40(CSI0_D2P)
CSI2_D3_N: J1.23 U25.41(CSI0_D3N)
CSI2_D3_P: J1.21 U25.42(CSI0_D3P)
CSI_TX_CLK_N: J20.7 U32.6(CSI_CLKN)
CSI_TX_CLK_P: J20.5 U32.5(CSI_CLKP)
CSI_TX_D0_N: J20.11 U32.4(CSI_D0N)
CSI_TX_D0_P: J20.9 U32.3(CSI_D0P)
CSI_TX_D1_N: J20.15 U32.2(CSI_D1N)
CSI_TX_D1_P: J20.13 U32.1(CSI_D1P)
CSI_TX_D2_N: J20.19 U32.32(CSI_D2N)
CSI_TX_D2_P: J20.17 U32.31(CSI_D2P)
CSI_TX_D3_N: J20.23 U32.30(CSI_D3N)
CSI_TX_D3_P: J20.21 U32.29(CSI_D3P)
DOUT_N: C406.2 U32.13(DOUT-)
DOUT_P: C405.2 U32.14(DOUT+)
GPIO0_HUB3: R200.2 U25.6(GPIO[0])
GPIO1_HUB3: R201.2 U25.7(GPIO[1])
HUB3_CK_O: TP23.1(TP) U25.14(CK_O/GPIO[8])
HUB3_CMLOUT0N: C298.1 R177.1 TP24.1(TP)
HUB3_CMLOUT0P: C299.1 R177.2 TP25.1(TP)
HUB3_CMLOUT1N: C284.1 R174.1 TP20.1(TP)
HUB3_CMLOUT1P: C283.1 R174.2 TP19.1(TP)
HUB3_CMLOUT2N: C276.1 R173.1 TP17.1(TP)
HUB3_CMLOUT2P: C277.1 R173.2 TP18.1(TP)
HUB3_CMLOUT3N: C289.1 R175.1 TP22.1(TP)
HUB3_CMLOUT3P: C286.1 R175.2 TP21.1(TP)
HUB3_I2C_SCL2: R170.1 U25.87(I2C_SCL2/GPIO[10])
HUB3_I2C_SDA2: R172.1 U25.88(I2C_SDA2/GPIO[9])
HUB3_IDX: R39.1 R171.2 U25.76(IDX)
HUB3_INTBn: J1.8 R178.1 U25.9(INTB/GPIO[3])
HUB3_LPF: C104.1 U25.77(LPF)
HUB3_MODE: R41.2 R42.1 U25.79(MODE)
HUB3_REF CLK: U25.15(REFCLK) ; also on sheet 10
HUB3_SYNC: J1.18 U25.8(GPIO[2])
HUB_RESETn: U25.61(PDB) ; also on sheet 4 5
LPF1_CAP: C408.1 U32.9(LPF1)
LPF2_CAP: C407.1 U32.12(LPF2)
R_971_REF CLK: R236.2 U32.20(CLKIN)
SoC_I2C6_SCL: U25.68(I2C_SCL) U32.24(I2C_SCL) ; also on sheet 4 5 10
SoC_I2C6_SDA: U25.67(I2C_SDA) U32.23(I2C_SDA) ; also on sheet 4 5 10
TESTEN3: R43.1 U25.60(TESTEN)

Not connected (* = marked no-connect by the designer): J1 2* 4* 6* 10* 14 22* 25* 26* 27* 28* 29* 31* 33* 35* 37* 39*; J20 1* 2 3* 4 6* 8 10 14 18 20 22* 30 32 34 36 38 40; U25 10(MOSI/GPIO[4])* 11(MISO/GPIO[5])* 12(SCK/GPIO[6])* 13(SS/GPIO[7])* 17(CSI2_CLK0N)* 18(CSI2_CLK0P)* 19(CSI2_D0N)* 20(CSI2_D0P)* 21(CSI2_D1N)* 22(CSI2_D1P)* 23(CSI2_CLK1N)* 24(CSI2_CLK1P)* 25(CSI2_D2N)* 26(CSI2_D2P)* 27(CSI2_D3N)* 28(CSI2_D3P)* 37(CSI0_CLK1N)* 38(CSI0_CLK1P)* 47(CSI1_CLK0N)* 48(CSI1_CLK0P)* 49(CSI1_D0N)* 50(CSI1_D0P)* 51(CSI1_D1N)* 52(CSI1_D1P)* 53(CSI1_CLK1N)* 54(CSI1_CLK1P)* 55(CSI1_D2N)* 56(CSI1_D2P)* 57(CSI1_D3N)* 58(CSI1_D3P)*; U32 22(RES1)*

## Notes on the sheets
sheet 6
- FPD Link IV to CSI-2 De-Serializer Hub - 3
- Note:Reset signal coming from same source on CP board
   for both CSI expansion connectors
- FPD LINK IV inputs
  from Camera
- 7'b I2C Address set to 0x32
- 100E
- 100E
- 100E
- [HUB3_INTBn]
- 100E
- 100E
- [HUB_RESETn]
- 100E
- 100E
- 100E
- [HUB3_SYNC]
- 100E
- [VCC_3V3]
- [VCC_CSI_IO - 3.3/1.8V]
- De-Serializer Hub3 Power  Filter
sheet 7
- CSI to FPD Link IV Serializer 971'
- 100E
- Silkscreen for J21:
  "CSI-TX FPD"
- 100E
- 100E
- 100E
- 100E
- NOTE: Additional signals are added for
   Internal testing purpose
- CSI Outputs from
  U9
- I2C 7b Address: 0X18
- Silkscreen for J20:
  "CSI-TX FPC"
- NON-Synchronous
  Mode (Default)
- R228: 10000Ohm
  R233: 4780Ohm
- Synchronous Mode
- R228: 10000Ohm
  R233: 402Ohm
